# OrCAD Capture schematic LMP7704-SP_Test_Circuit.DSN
size A; title: LMP7704-SP Radiation Hardness Assured (RHA), Precision,; rev: 1.3; note: Datasheet: SNOSDB6C   EVM: N/A
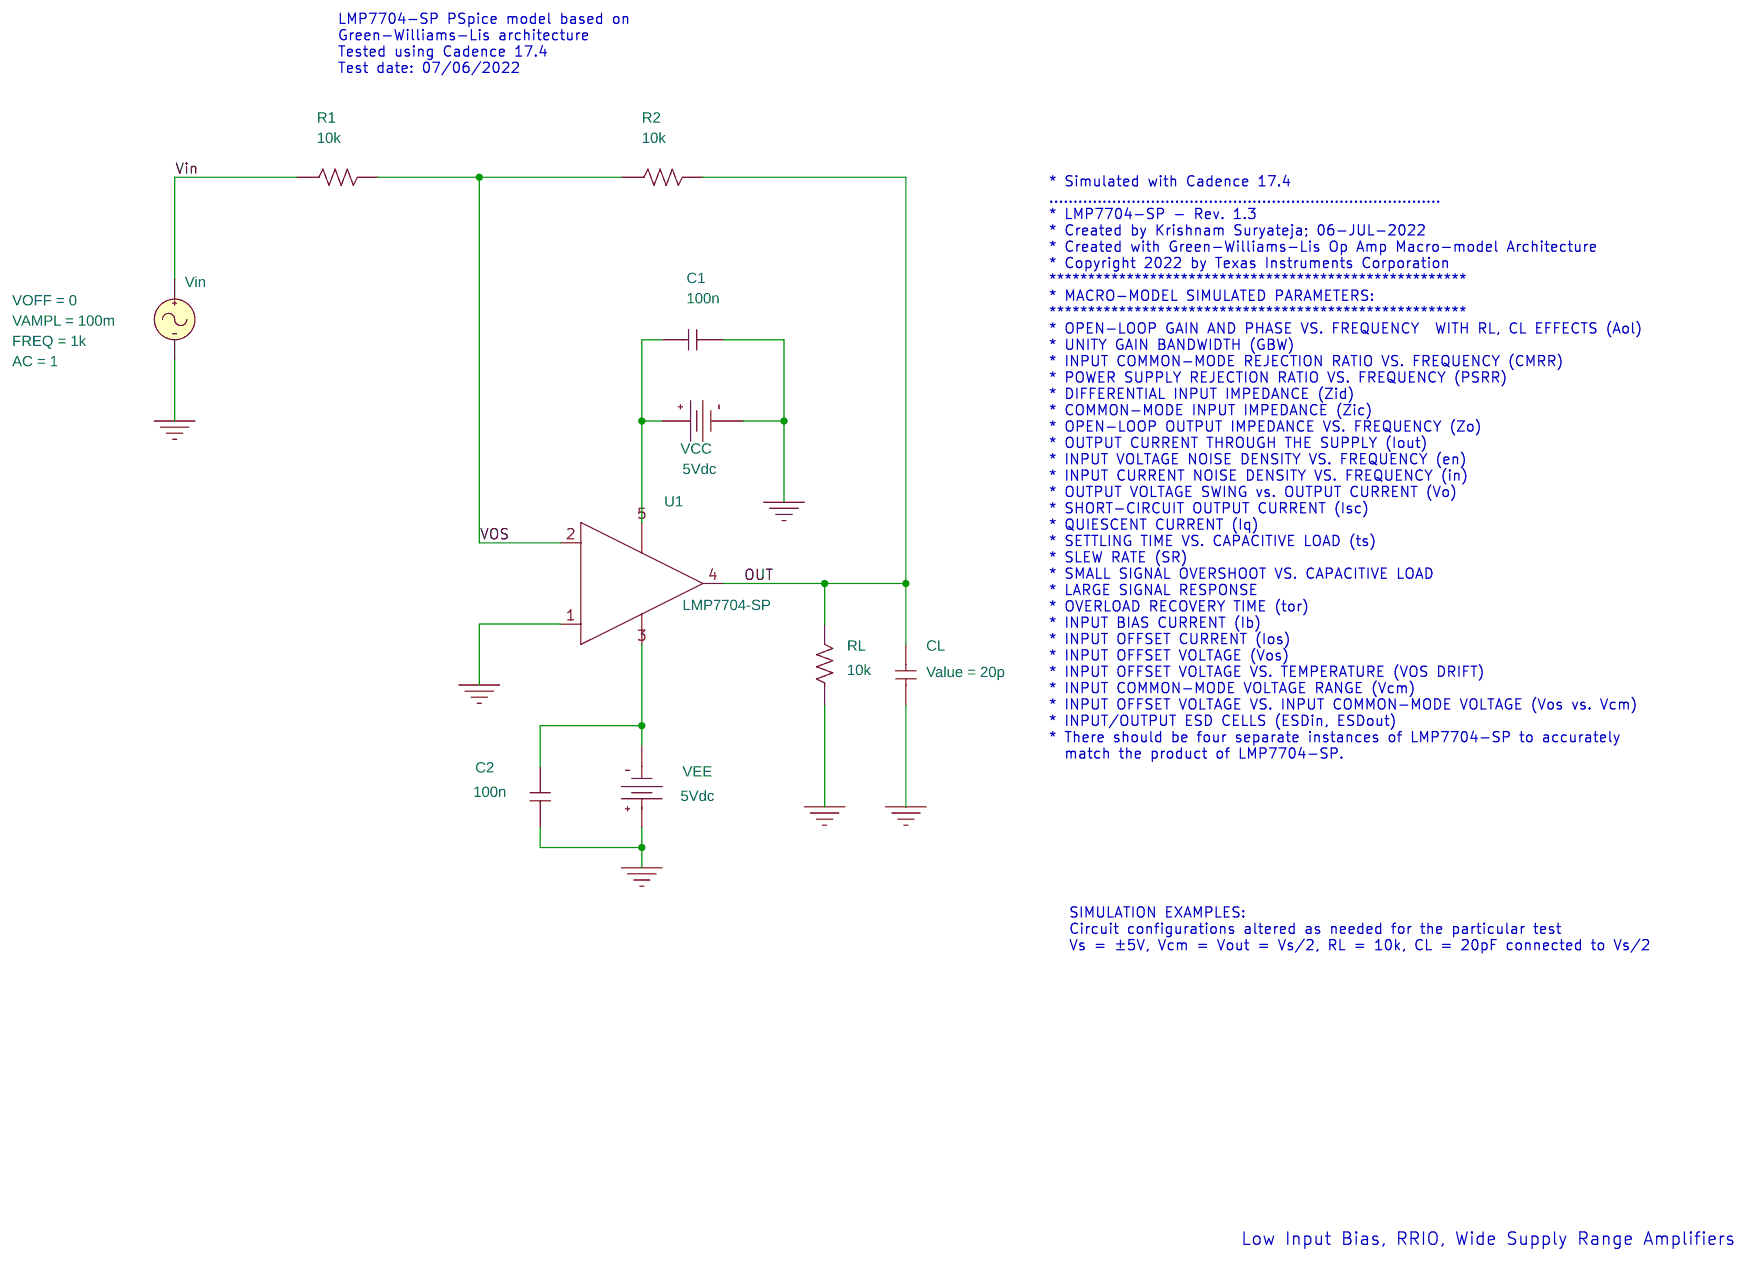
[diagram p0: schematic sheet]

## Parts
C1  100n  [cap196]
C2  100n  [cap196]
CL  20p  [cap196]
R1  10k  [AXRC05]
R2  10k  [AXRC05]
RL  10k  [AXRC05]
U1  LMP7704-SP
VCC  VDC
VEE  VDC
Vin  VSIN

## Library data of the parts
C1 C2 CL = C
R1 R2 RL = R
U1 = LMP7704-SP
VCC VEE = VDC: DC: 5Vdc
Vin = VSIN: AC: 1; FREQ: 1k; VAMPL: 100m; VOFF: 0

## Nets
Vin: R1.1 Vin.1(+)
0: C1.2 C2.1 CL.2 RL.1 U1.1(+) VCC.1(-) VEE.0(+) Vin.2(-)
OUT: CL.1 R2.2 RL.2 U1.4(OUT)
VOS: R1.2 R2.1 U1.2(-)
N27303: C1.1 U1.5(V+) VCC.0(+)
N27354: C2.2 U1.3(V-) VEE.1(-)

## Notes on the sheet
- LMP7704-SP PSpice model based on
  Green-Williams-Lis architecture
  Tested using Cadence 17.4
  Test date: 07/06/2022
- * Simulated with Cadence 17.4
  .................................................................................
  * LMP7704-SP - Rev. 1.3
  * Created by Krishnam Suryateja; 06-JUL-2022
  * Created with Green-Williams-Lis Op Amp Macro-model Architecture
  * Copyright 2022 by Texas Instruments Corporation
  ******************************************************
  * MACRO-MODEL SIMULATED PARAMETERS:
  ******************************************************
  * OPEN-LOOP GAIN AND PHASE VS. FREQUENCY  WITH RL, CL EFFECTS (Aol)
  * UNITY GAIN BANDWIDTH (GBW)
  * INPUT COMMON-MODE REJECTION RATIO VS. FREQUENCY (CMRR)
  * POWER SUPPLY REJECTION RATIO VS. FREQUENCY (PSRR)
  * DIFFERENTIAL INPUT IMPEDANCE (Zid)
  * COMMON-MODE INPUT IMPEDANCE (Zic)
  * OPEN-LOOP OUTPUT IMPEDANCE VS. FREQUENCY (Zo)
  * OUTPUT CURRENT THROUGH THE SUPPLY (Iout)
  * INPUT VOLTAGE NOISE DENSITY VS. FREQUENCY (en)
  * INPUT CURRENT NOISE DENSITY VS. FREQUENCY (in)
  * OUTPUT VOLTAGE SWING vs. OUTPUT CURRENT (Vo)
  * SHORT-CIRCUIT OUTPUT CURRENT (Isc)
  * QUIESCENT CURRENT (Iq)
  * SETTLING TIME VS. CAPACITIVE LOAD (ts)
  * SLEW RATE (SR)
  * SMALL SIGNAL OVERSHOOT VS. CAPACITIVE LOAD
  * LARGE SIGNAL RESPONSE
  * OVERLOAD RECOVERY TIME (tor)
  * INPUT BIAS CURRENT (Ib)
  * INPUT OFFSET CURRENT (Ios)
  * INPUT OFFSET VOLTAGE (Vos)
  * INPUT OFFSET VOLTAGE VS. TEMPERATURE (VOS DRIFT)
  * INPUT COMMON-MODE VOLTAGE RANGE (Vcm)
  * INPUT OFFSET VOLTAGE VS. INPUT COMMON-MODE VOLTAGE (Vos vs. Vcm)
  * INPUT/OUTPUT ESD CELLS (ESDin, ESDout)
  * There should be four separate instances of LMP7704-SP to accurately
    match the product of LMP7704-SP.
- SIMULATION EXAMPLES:
  Circuit configurations altered as needed for the particular test
  Vs = ±5V, Vcm = Vout = Vs/2, RL = 10k, CL = 20pF connected to Vs/2
- Low Input Bias, RRIO, Wide Supply Range Amplifiers
